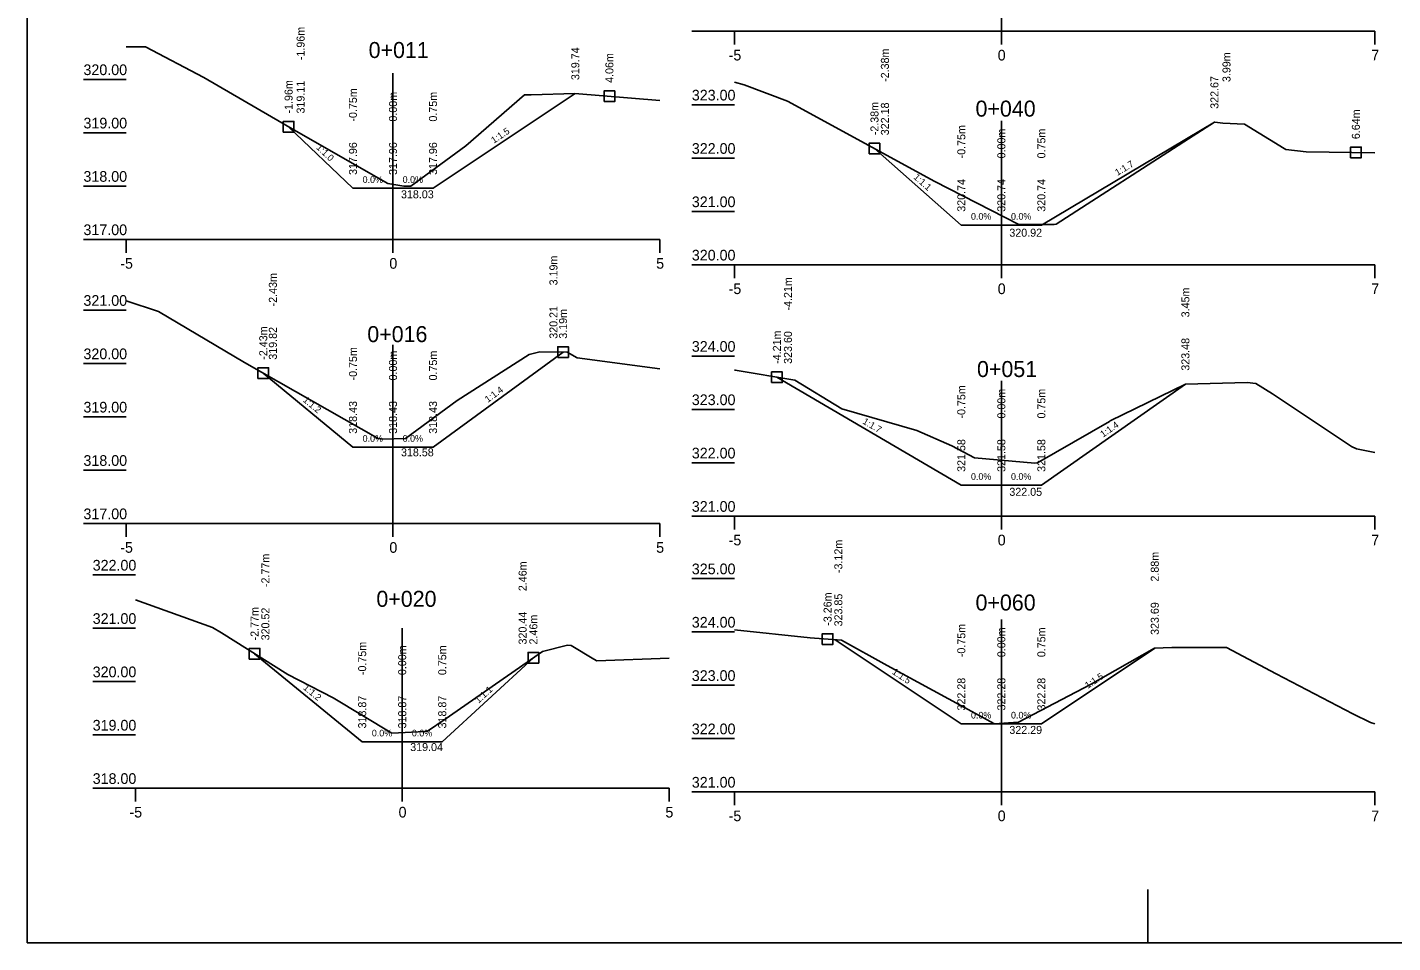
# Model space of a CAD drawing. Extents: x -558995.4 to -558953.4, y -1164517.9 to -1164488.2.
# Drawn here: x -558995.41 to -558969.83, y -1164517.88 to -1164500.72 of the extents above; entities that cross this region are included whole.
import ezdxf

# ---------------------------------------------------------------- set-up
doc = ezdxf.new("R2010")
doc.units = 0
for name, color, linetype in [('16', 7, 'Continuous'), ('21', 7, 'Continuous'), ('28', 7, 'Continuous'), ('59', 7, 'Continuous'), ('Body pricny rez', 7, 'Continuous'), ('Hranice_pozemku', 7, 'Continuous'), ('Popis pricneho profilu', 7, 'Continuous')]:
    doc.layers.add(name, color=color, linetype=linetype)

msp = doc.modelspace()

# ---------------------------------------------------------------- linework, layer by layer
for p, q in [((-558995.413, -1164488.18), (-558995.413, -1164517.88)), ((-558974.413, -1164517.88), (-558974.413, -1164516.88)), ((-558995.413, -1164517.88), (-558953.413, -1164517.88))]:
    msp.add_line(p, q)
for points in [[(-558993.561, -1164501.084), (-558993.197, -1164501.083), (-558992.103, -1164501.658), (-558990.372, -1164502.668), (-558988.655, -1164503.646), (-558988.357, -1164503.698), (-558988.225, -1164503.695), (-558987.195, -1164502.939), (-558986.096, -1164501.985), (-558985.974, -1164501.986), (-558985.154, -1164501.957), (-558983.561, -1164502.088)], [(-558982.161, -1164501.744), (-558981.983, -1164501.798), (-558981.168, -1164502.105), (-558978.405, -1164503.608), (-558976.836, -1164504.416), (-558976.174, -1164504.418), (-558976.135, -1164504.412), (-558973.654, -1164502.809), (-558973.168, -1164502.496), (-558973.163, -1164502.497), (-558973.013, -1164502.514), (-558972.607, -1164502.536), (-558971.862, -1164502.991), (-558971.828, -1164503.006), (-558971.449, -1164503.05), (-558970.161, -1164503.071)], [(-558990.517, -1164502.584), (-558989.311, -1164503.736), (-558988.561, -1164503.736), (-558987.811, -1164503.736), (-558985.144, -1164501.958)], [(-558987.811, -1164503.736), (-558985.144, -1164501.958)], [(-558976.411, -1164504.426), (-558973.168, -1164502.496)], [(-558989.311, -1164503.736), (-558990.517, -1164502.584)], [(-558977.911, -1164504.426), (-558979.538, -1164502.992)], [(-558988.561, -1164503.736), (-558989.311, -1164503.736)], [(-558988.561, -1164503.736), (-558987.811, -1164503.736)], [(-558977.161, -1164504.426), (-558977.911, -1164504.426)], [(-558977.161, -1164504.426), (-558976.411, -1164504.426)], [(-558993.561, -1164505.849), (-558992.954, -1164506.044), (-558991.341, -1164507.001), (-558988.837, -1164508.427), (-558988.76, -1164508.44), (-558988.328, -1164508.43), (-558987.357, -1164507.717), (-558986.007, -1164506.852), (-558985.811, -1164506.804), (-558985.295, -1164506.808), (-558985.112, -1164506.918), (-558983.561, -1164507.121)], [(-558990.992, -1164507.2), (-558989.311, -1164508.589), (-558988.561, -1164508.589), (-558987.811, -1164508.589), (-558985.374, -1164506.807)], [(-558987.811, -1164508.589), (-558985.374, -1164506.807)], [(-558989.311, -1164508.589), (-558990.992, -1164507.2)], [(-558982.161, -1164507.142), (-558982.15, -1164507.144), (-558981.028, -1164507.336), (-558980.148, -1164507.869), (-558978.746, -1164508.276), (-558978.087, -1164508.563), (-558977.662, -1164508.787), (-558976.532, -1164508.888), (-558976.495, -1164508.885), (-558976.486, -1164508.885), (-558975.136, -1164508.106), (-558975.12, -1164508.097), (-558973.712, -1164507.406), (-558972.553, -1164507.379), (-558972.393, -1164507.394), (-558972.082, -1164507.592), (-558970.602, -1164508.576), (-558970.504, -1164508.622), (-558970.161, -1164508.688)], [(-558977.911, -1164509.303), (-558981.367, -1164507.278)], [(-558976.411, -1164509.303), (-558973.712, -1164507.406)], [(-558988.561, -1164508.589), (-558989.311, -1164508.589)], [(-558988.561, -1164508.589), (-558987.811, -1164508.589)], [(-558977.161, -1164509.303), (-558977.911, -1164509.303)], [(-558977.161, -1164509.303), (-558976.411, -1164509.303)], [(-558993.388, -1164511.451), (-558991.946, -1164511.969), (-558991.777, -1164512.072), (-558990.532, -1164512.852), (-558989.684, -1164513.292), (-558988.583, -1164513.954), (-558987.963, -1164513.92), (-558987.912, -1164513.915), (-558987.581, -1164513.688), (-558985.757, -1164512.419), (-558985.292, -1164512.304), (-558985.223, -1164512.308), (-558984.796, -1164512.562), (-558984.742, -1164512.598), (-558983.388, -1164512.546)], [(-558982.161, -1164512.013), (-558980.742, -1164512.162), (-558980.158, -1164512.209), (-558979.303, -1164512.681), (-558977.292, -1164513.775), (-558977.024, -1164513.756), (-558976.842, -1164513.747), (-558975.49, -1164513.041), (-558974.29, -1164512.36), (-558973.966, -1164512.346), (-558972.939, -1164512.345), (-558972.01, -1164512.84), (-558970.577, -1164513.59), (-558970.242, -1164513.749), (-558970.161, -1164513.777)], [(-558980.277, -1164512.2), (-558977.911, -1164513.777), (-558977.161, -1164513.777), (-558976.411, -1164513.777), (-558974.286, -1164512.36)], [(-558977.911, -1164513.777), (-558980.277, -1164512.2)], [(-558991.155, -1164512.462), (-558989.138, -1164514.113), (-558988.388, -1164514.113), (-558987.638, -1164514.113), (-558985.93, -1164512.539)], [(-558989.138, -1164514.113), (-558991.155, -1164512.462)], [(-558976.411, -1164513.777), (-558974.286, -1164512.36)], [(-558987.638, -1164514.113), (-558985.93, -1164512.539)], [(-558977.161, -1164513.777), (-558977.911, -1164513.777)], [(-558977.161, -1164513.777), (-558976.411, -1164513.777)], [(-558988.388, -1164514.113), (-558989.138, -1164514.113)], [(-558988.388, -1164514.113), (-558987.638, -1164514.113)]]:
    msp.add_lwpolyline(points)
at = {"layer": '16'}
for p, q in [((-558982.161, -1164500.79), (-558970.161, -1164500.79)), ((-558993.561, -1164504.694), (-558983.561, -1164504.694)), ((-558982.161, -1164505.17), (-558970.161, -1164505.17)), ((-558982.161, -1164509.881), (-558970.161, -1164509.881)), ((-558993.561, -1164510.02), (-558983.561, -1164510.02)), ((-558993.388, -1164514.983), (-558983.388, -1164514.983)), ((-558982.161, -1164515.052), (-558970.161, -1164515.052))]:
    msp.add_line(p, q, dxfattribs=at)
at = {"layer": '21'}
for p, q in [((-558982.961, -1164500.79), (-558982.161, -1164500.79)), ((-558994.361, -1164501.694), (-558993.561, -1164501.694)), ((-558982.961, -1164502.17), (-558982.161, -1164502.17)), ((-558994.361, -1164502.694), (-558993.561, -1164502.694)), ((-558982.961, -1164503.17), (-558982.161, -1164503.17)), ((-558994.361, -1164503.694), (-558993.561, -1164503.694)), ((-558982.961, -1164504.17), (-558982.161, -1164504.17)), ((-558994.361, -1164504.694), (-558993.561, -1164504.694)), ((-558982.961, -1164505.17), (-558982.161, -1164505.17)), ((-558994.361, -1164506.02), (-558993.561, -1164506.02)), ((-558982.961, -1164506.881), (-558982.161, -1164506.881)), ((-558994.361, -1164507.02), (-558993.561, -1164507.02)), ((-558982.961, -1164507.881), (-558982.161, -1164507.881)), ((-558994.361, -1164508.02), (-558993.561, -1164508.02)), ((-558982.961, -1164508.881), (-558982.161, -1164508.881)), ((-558994.361, -1164509.02), (-558993.561, -1164509.02)), ((-558982.961, -1164509.881), (-558982.161, -1164509.881)), ((-558994.361, -1164510.02), (-558993.561, -1164510.02)), ((-558994.188, -1164510.983), (-558993.388, -1164510.983)), ((-558982.961, -1164511.052), (-558982.161, -1164511.052)), ((-558994.188, -1164511.983), (-558993.388, -1164511.983)), ((-558982.961, -1164512.052), (-558982.161, -1164512.052)), ((-558994.188, -1164512.983), (-558993.388, -1164512.983)), ((-558982.961, -1164513.052), (-558982.161, -1164513.052)), ((-558994.188, -1164513.983), (-558993.388, -1164513.983)), ((-558982.961, -1164514.052), (-558982.161, -1164514.052)), ((-558994.188, -1164514.983), (-558993.388, -1164514.983)), ((-558982.961, -1164515.052), (-558982.161, -1164515.052))]:
    msp.add_line(p, q, dxfattribs=at)
at = {"layer": '28'}
for p, q in [((-558977.161, -1164498.112), (-558977.161, -1164500.79)), ((-558988.561, -1164501.58), (-558988.561, -1164504.694)), ((-558977.161, -1164502.471), (-558977.161, -1164505.17)), ((-558988.561, -1164506.669), (-558988.561, -1164510.02)), ((-558977.161, -1164507.348), (-558977.161, -1164509.881)), ((-558988.388, -1164511.983), (-558988.388, -1164514.983)), ((-558977.161, -1164511.823), (-558977.161, -1164515.052))]:
    msp.add_line(p, q, dxfattribs=at)
at = {"layer": '59'}
for p, q in [((-558982.161, -1164501.04), (-558982.161, -1164500.79)), ((-558977.161, -1164501.04), (-558977.161, -1164500.79)), ((-558970.161, -1164501.04), (-558970.161, -1164500.79)), ((-558993.561, -1164504.944), (-558993.561, -1164504.694)), ((-558988.561, -1164504.944), (-558988.561, -1164504.694)), ((-558983.561, -1164504.944), (-558983.561, -1164504.694)), ((-558982.161, -1164505.42), (-558982.161, -1164505.17)), ((-558977.161, -1164505.42), (-558977.161, -1164505.17)), ((-558970.161, -1164505.42), (-558970.161, -1164505.17)), ((-558982.161, -1164510.131), (-558982.161, -1164509.881)), ((-558977.161, -1164510.131), (-558977.161, -1164509.881)), ((-558970.161, -1164510.131), (-558970.161, -1164509.881)), ((-558993.561, -1164510.27), (-558993.561, -1164510.02)), ((-558988.561, -1164510.27), (-558988.561, -1164510.02)), ((-558983.561, -1164510.27), (-558983.561, -1164510.02)), ((-558993.388, -1164515.233), (-558993.388, -1164514.983)), ((-558988.388, -1164515.233), (-558988.388, -1164514.983)), ((-558983.388, -1164515.233), (-558983.388, -1164514.983)), ((-558982.161, -1164515.302), (-558982.161, -1164515.052)), ((-558977.161, -1164515.302), (-558977.161, -1164515.052)), ((-558970.161, -1164515.302), (-558970.161, -1164515.052))]:
    msp.add_line(p, q, dxfattribs=at)
at = {"layer": 'Hranice_pozemku'}
for points in [[(-558984.606, -1164502.11), (-558984.406, -1164502.11), (-558984.406, -1164501.91), (-558984.606, -1164501.91)], [(-558990.617, -1164502.684), (-558990.417, -1164502.684), (-558990.417, -1164502.484), (-558990.617, -1164502.484)], [(-558979.638, -1164503.092), (-558979.438, -1164503.092), (-558979.438, -1164502.892), (-558979.638, -1164502.892)], [(-558970.618, -1164503.165), (-558970.418, -1164503.165), (-558970.418, -1164502.965), (-558970.618, -1164502.965)], [(-558985.474, -1164506.907), (-558985.274, -1164506.907), (-558985.274, -1164506.707), (-558985.474, -1164506.707)], [(-558991.092, -1164507.3), (-558990.892, -1164507.3), (-558990.892, -1164507.1), (-558991.092, -1164507.1)], [(-558981.467, -1164507.378), (-558981.267, -1164507.378), (-558981.267, -1164507.178), (-558981.467, -1164507.178)], [(-558980.517, -1164512.288), (-558980.317, -1164512.288), (-558980.317, -1164512.088), (-558980.517, -1164512.088)], [(-558991.255, -1164512.562), (-558991.055, -1164512.562), (-558991.055, -1164512.362), (-558991.255, -1164512.362)], [(-558986.03, -1164512.639), (-558985.83, -1164512.639), (-558985.83, -1164512.439), (-558986.03, -1164512.439)]]:
    msp.add_lwpolyline(points, close=True, dxfattribs=at)

# ---------------------------------------------------------------- texts
for s, p in [('0+011', (-558989.017, -1164501.294)), ('0+040', (-558977.645, -1164502.393)), ('0+016', (-558989.042, -1164506.62)), ('0+051', (-558977.617, -1164507.275)), ('0+020', (-558988.872, -1164511.583)), ('0+060', (-558977.645, -1164511.652))]:
    msp.add_text(s, height=0.3).set_placement(p)
for s, rotation, p in [('1:1.5', 33.6901, (-558986.671, -1164502.901)), ('1:1.0', 316.2875, (-558990.008, -1164502.984)), ('1:1.7', 30.7595, (-558974.985, -1164503.505)), ('1:1.1', 318.6022, (-558978.817, -1164503.544)), ('1:1.4', 36.1715, (-558986.783, -1164507.76)), ('1:1.2', 320.4105, (-558990.258, -1164507.725)), ('1:1.7', 329.6276, (-558979.772, -1164508.141)), ('1:1.4', 35.1059, (-558975.253, -1164508.413)), ('1:1.5', 326.3099, (-558979.218, -1164512.83)), ('1:1.5', 33.6901, (-558975.542, -1164513.122)), ('1:1.2', 320.6976, (-558990.254, -1164513.119)), ('1:1.1', 42.645, (-558986.957, -1164513.401))]:
    msp.add_text(s, height=0.125, rotation=rotation).set_placement(p)
at = {"layer": '16'}
for p in [(-558989.13, -1164503.636), (-558988.38, -1164503.636), (-558977.73, -1164504.326), (-558976.98, -1164504.326), (-558989.13, -1164508.489), (-558988.38, -1164508.489), (-558977.73, -1164509.203), (-558976.98, -1164509.203), (-558977.73, -1164513.677), (-558976.98, -1164513.677), (-558988.957, -1164514.013), (-558988.207, -1164514.013)]:
    msp.add_text('0.0%', height=0.125, dxfattribs=at).set_placement(p)
at = {"layer": '21'}
for s, p in [('-5', (-558982.272, -1164501.34)), ('0', (-558977.229, -1164501.34)), ('7', (-558970.229, -1164501.34)), ('320.00', (-558994.361, -1164501.614)), ('323.00', (-558982.961, -1164502.09)), ('319.00', (-558994.361, -1164502.614)), ('322.00', (-558982.961, -1164503.09)), ('318.00', (-558994.361, -1164503.614)), ('321.00', (-558982.961, -1164504.09)), ('317.00', (-558994.361, -1164504.614)), ('-5', (-558993.672, -1164505.244)), ('0', (-558988.629, -1164505.244)), ('5', (-558983.629, -1164505.244)), ('320.00', (-558982.961, -1164505.09)), ('-5', (-558982.272, -1164505.72)), ('0', (-558977.229, -1164505.72)), ('7', (-558970.229, -1164505.72)), ('321.00', (-558994.361, -1164505.94)), ('324.00', (-558982.961, -1164506.801)), ('320.00', (-558994.361, -1164506.94)), ('323.00', (-558982.961, -1164507.801)), ('319.00', (-558994.361, -1164507.94)), ('322.00', (-558982.961, -1164508.801)), ('318.00', (-558994.361, -1164508.94)), ('321.00', (-558982.961, -1164509.801)), ('317.00', (-558994.361, -1164509.94)), ('-5', (-558993.672, -1164510.57)), ('0', (-558988.629, -1164510.57)), ('5', (-558983.629, -1164510.57)), ('-5', (-558982.272, -1164510.431)), ('0', (-558977.229, -1164510.431)), ('7', (-558970.229, -1164510.431)), ('322.00', (-558994.188, -1164510.903)), ('325.00', (-558982.961, -1164510.972)), ('321.00', (-558994.188, -1164511.903)), ('324.00', (-558982.961, -1164511.972)), ('320.00', (-558994.188, -1164512.903)), ('323.00', (-558982.961, -1164512.972)), ('319.00', (-558994.188, -1164513.903)), ('322.00', (-558982.961, -1164513.972)), ('318.00', (-558994.188, -1164514.903)), ('321.00', (-558982.961, -1164514.972)), ('-5', (-558993.499, -1164515.533)), ('0', (-558988.456, -1164515.533)), ('5', (-558983.456, -1164515.533)), ('-5', (-558982.272, -1164515.602)), ('0', (-558977.229, -1164515.602)), ('7', (-558970.229, -1164515.602))]:
    msp.add_text(s, height=0.2, dxfattribs=at).set_placement(p)
at = {"layer": '59'}
for s, p in [('318.03', (-558988.411, -1164503.924)), ('318.03', (-558988.411, -1164503.924)), ('320.92', (-558977.011, -1164504.644)), ('320.92', (-558977.011, -1164504.644)), ('318.58', (-558988.411, -1164508.761)), ('318.58', (-558988.411, -1164508.761)), ('322.05', (-558977.011, -1164509.502)), ('322.05', (-558977.011, -1164509.502)), ('322.29', (-558977.011, -1164513.966)), ('322.29', (-558977.011, -1164513.966)), ('319.04', (-558988.238, -1164514.287))]:
    msp.add_text(s, height=0.15, dxfattribs=at).set_placement(p)
at = {"layer": 'Body pricny rez'}
for p in [(-558985.144, -1164501.958), (-558973.169, -1164502.497), (-558990.517, -1164502.584), (-558979.539, -1164502.992), (-558989.312, -1164503.737), (-558988.562, -1164503.737), (-558987.812, -1164503.737), (-558977.912, -1164504.427), (-558977.162, -1164504.427), (-558976.412, -1164504.427), (-558985.374, -1164506.808), (-558990.992, -1164507.2), (-558981.367, -1164507.279), (-558973.712, -1164507.406), (-558989.312, -1164508.59), (-558988.562, -1164508.59), (-558987.812, -1164508.59), (-558977.912, -1164509.304), (-558977.162, -1164509.304), (-558976.412, -1164509.304), (-558980.277, -1164512.2), (-558991.155, -1164512.463), (-558974.287, -1164512.36), (-558985.93, -1164512.54), (-558977.912, -1164513.777), (-558977.162, -1164513.777), (-558976.412, -1164513.777), (-558989.139, -1164514.113), (-558988.389, -1164514.113), (-558987.639, -1164514.113)]:
    msp.add_text('+', height=0.001, dxfattribs=at).set_placement(p)
at = {"layer": 'Popis pricneho profilu'}
for s, p in [('-1.96m', (-558990.217, -1164501.334)), ('319.74', (-558985.069, -1164501.708)), ('4.06m', (-558984.431, -1164501.76)), ('-2.38m', (-558979.268, -1164501.742)), ('3.99m', (-558972.867, -1164501.745)), ('-1.96m', (-558990.442, -1164502.334)), ('319.11', (-558990.217, -1164502.334)), ('322.67', (-558973.093, -1164502.246)), ('-0.75m', (-558989.236, -1164502.486)), ('0.00m', (-558988.486, -1164502.486)), ('0.75m', (-558987.736, -1164502.486)), ('-2.38m', (-558979.463, -1164502.742)), ('322.18', (-558979.268, -1164502.742)), ('6.64m', (-558970.443, -1164502.815)), ('-0.75m', (-558977.836, -1164503.176)), ('0.00m', (-558977.086, -1164503.176)), ('0.75m', (-558976.336, -1164503.176)), ('317.96', (-558989.236, -1164503.486)), ('317.96', (-558988.486, -1164503.486)), ('317.96', (-558987.736, -1164503.486)), ('320.74', (-558977.836, -1164504.176)), ('320.74', (-558977.086, -1164504.176)), ('320.74', (-558976.336, -1164504.176)), ('3.19m', (-558985.479, -1164505.557)), ('-2.43m', (-558990.737, -1164505.95)), ('-4.21m', (-558981.085, -1164506.028)), ('3.45m', (-558973.637, -1164506.156)), ('320.21', (-558985.479, -1164506.557)), ('3.19m', (-558985.299, -1164506.557)), ('-2.43m', (-558990.917, -1164506.95)), ('319.82', (-558990.737, -1164506.95)), ('-4.21m', (-558981.292, -1164507.028)), ('323.60', (-558981.085, -1164507.028)), ('323.48', (-558973.637, -1164507.156)), ('-0.75m', (-558989.236, -1164507.339)), ('0.00m', (-558988.486, -1164507.339)), ('0.75m', (-558987.736, -1164507.339)), ('-0.75m', (-558977.836, -1164508.053)), ('0.00m', (-558977.086, -1164508.053)), ('0.75m', (-558976.336, -1164508.053)), ('318.43', (-558989.236, -1164508.339)), ('318.43', (-558988.486, -1164508.339)), ('318.43', (-558987.736, -1164508.339)), ('321.58', (-558977.836, -1164509.053)), ('321.58', (-558977.086, -1164509.053)), ('321.58', (-558976.336, -1164509.053)), ('-3.12m', (-558980.14, -1164510.95)), ('-2.77m', (-558990.877, -1164511.212)), ('2.88m', (-558974.211, -1164511.11)), ('2.46m', (-558986.057, -1164511.289)), ('-3.26m', (-558980.342, -1164511.938)), ('323.85', (-558980.14, -1164511.95)), ('-2.77m', (-558991.08, -1164512.212)), ('320.52', (-558990.877, -1164512.212)), ('320.44', (-558986.057, -1164512.289)), ('2.46m', (-558985.855, -1164512.289)), ('323.69', (-558974.211, -1164512.11)), ('-0.75m', (-558977.836, -1164512.527)), ('0.00m', (-558977.086, -1164512.527)), ('0.75m', (-558976.336, -1164512.527)), ('-0.75m', (-558989.063, -1164512.863)), ('0.00m', (-558988.313, -1164512.863)), ('0.75m', (-558987.563, -1164512.863)), ('322.28', (-558977.836, -1164513.527)), ('322.28', (-558977.086, -1164513.527)), ('322.28', (-558976.336, -1164513.527)), ('318.87', (-558989.063, -1164513.863)), ('318.87', (-558988.313, -1164513.863)), ('318.87', (-558987.563, -1164513.863))]:
    msp.add_text(s, height=0.15, rotation=90, dxfattribs=at).set_placement(p)

doc.saveas('drawing.dxf')
